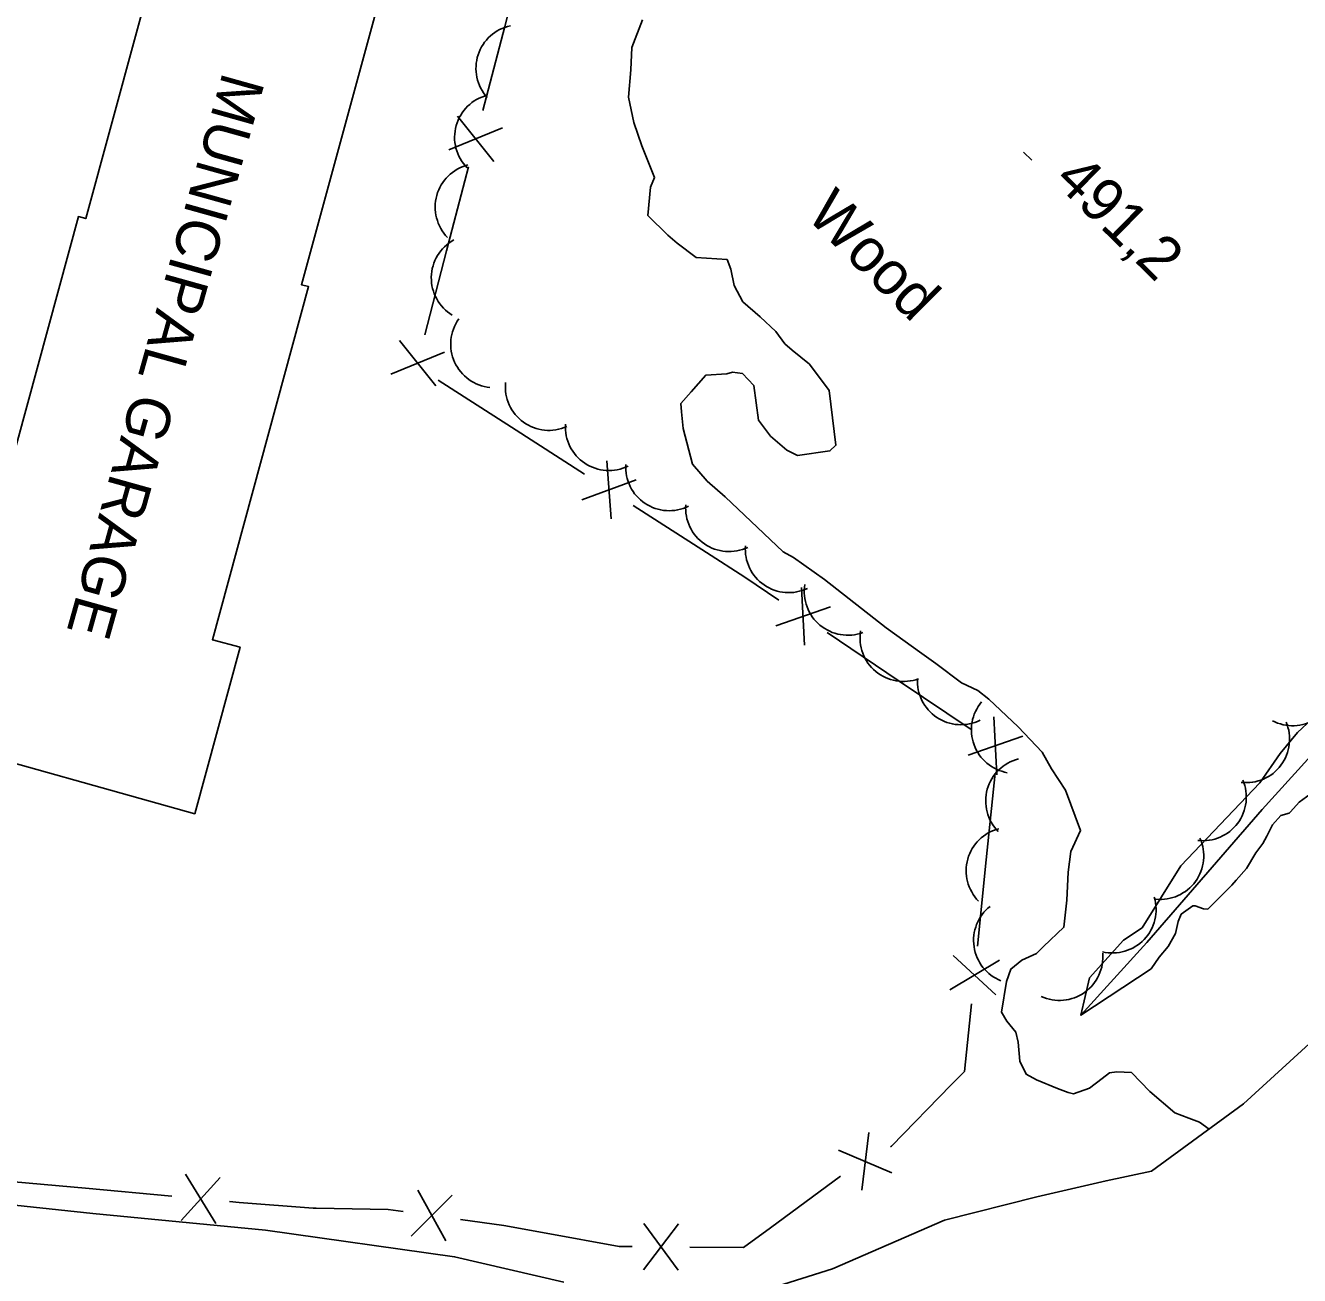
# Model space of a CAD drawing. Extents: x 642515 to 647219, y 6080136 to 6084356.
# Drawn here: x 643658.8 to 643746.7, y 6081612.4 to 6081698.7 of the extents above; entities that cross this region are included whole.
import ezdxf

# ---------------------------------------------------------------- set-up
doc = ezdxf.new("R2010")
doc.units = 0
for name, color, linetype in [('Level 1', 7, 'Continuous'), ('Level 19', 7, 'Continuous'), ('Level 2', 7, 'Continuous'), ('Level 3', 7, 'Continuous'), ('Level 31', 7, 'Continuous'), ('Level 37', 7, 'Continuous'), ('Level 4', 7, 'Continuous'), ('Level 44', 7, 'Continuous')]:
    doc.layers.add(name, color=color, linetype=linetype)

msp = doc.modelspace()

# ---------------------------------------------------------------- linework, layer by layer
at = {"layer": 'Level 1'}
msp.add_lwpolyline([(643747.429, 6081645.636), (643746.659, 6081645.102), (643746.061, 6081644.418), (643745.986, 6081644.332), (643745.393, 6081644.172), (643744.832, 6081643.531), (643744.443, 6081642.74), (643744.155, 6081642.238), (643743.674, 6081641.602), (643743.023, 6081640.511), (643742.313, 6081639.699), (643742.014, 6081639.357), (643740.353, 6081637.716), (643740.069, 6081637.738), (643739.491, 6081637.942), (643739.331, 6081637.931), (643738.524, 6081637.354), (643738.316, 6081636.857), (643738.13, 6081636.039), (643737.628, 6081635.12), (643736.993, 6081634.393), (643736.443, 6081633.591), (643731.596, 6081630.381), (643732.186, 6081632.958), (643734.547, 6081635.571), (643735.819, 6081636.42), (643738.509, 6081640.707), (643743.962, 6081646.425), (643745.355, 6081648.45), (643746.546, 6081649.899), (643748.592, 6081651.806)], dxfattribs=at)
at = {"layer": 'Level 19'}
for points in [[(643748.154, 6081629.154), (643742.826, 6081624.278), (643736.477, 6081619.617), (643733.333, 6081618.964), (643728.567, 6081617.84), (643722.18, 6081616.245), (643714.459, 6081612.868), (643708.535, 6081611.022)], [(643695.902, 6081611.955), (643688.373, 6081613.712), (643675.32, 6081615.544), (643663.399, 6081616.686), (643645.712, 6081618.573), (643643.905, 6081619.098), (643643.077, 6081620.655), (643642.485, 6081622.886)]]:
    msp.add_lwpolyline(points, dxfattribs=at)
at = {"layer": 'Level 2'}
for points in [[(643704.704, 6081673.419), (643705.712, 6081674.571), (643707.154, 6081674.666), (643707.549, 6081674.773), (643708.238, 6081674.697), (643709.018, 6081673.864), (643709.342, 6081671.472), (643710.181, 6081670.362), (643711.293, 6081669.389), (643712.041, 6081669.036), (643714.273, 6081669.344), (643714.689, 6081669.734), (643714.23, 6081673.524), (643712.861, 6081675.324), (643711.669, 6081676.291), (643711.156, 6081676.74), (643710.536, 6081677.583), (643709.461, 6081678.598), (643708.264, 6081679.645), (643707.664, 6081680.772), (643707.428, 6081681.883), (643707.181, 6081682.55), (643705.04, 6081682.69), (643703.725, 6081683.689), (643703.084, 6081684.25), (643701.705, 6081685.607), (643701.894, 6081687.55), (643702.171, 6081688.211), (643701.298, 6081690.406), (643700.746, 6081692.018), (643700.386, 6081693.764), (643700.539, 6081695.664), (643700.596, 6081697.195), (643701.352, 6081699.095)], [(643740.446, 6081622.53), (643739.789, 6081623.003), (643739.046, 6081623.276), (643738.095, 6081623.655), (643736.347, 6081625.109), (643735.09, 6081626.434), (643734.081, 6081626.488), (643733.563, 6081626.414), (643733.067, 6081626.019), (643732.187, 6081625.357), (643731.087, 6081624.963), (643730.718, 6081625.059), (643729.976, 6081625.332), (643728.528, 6081625.921), (643727.817, 6081626.316), (643727.394, 6081627.213), (643727.264, 6081628.532), (643727.098, 6081629.205), (643726.483, 6081629.969), (643726.119, 6081630.589), (643726.458, 6081632.703), (643726.761, 6081633.567), (643727.524, 6081634.181), (643728.538, 6081634.65), (643729.028, 6081635.125), (643730.426, 6081636.464), (643730.621, 6081638.327), (643730.731, 6081640.265), (643730.916, 6081641.685), (643731.581, 6081643.136), (643730.547, 6081645.924), (643729.562, 6081647.387), (643728.92, 6081648.552), (643727.273, 6081650.293), (643725.252, 6081652.211), (643724.488, 6081652.804), (643723.366, 6081653.334), (643721.586, 6081654.664), (643720.613, 6081655.364), (643718.16, 6081657.133), (643713.91, 6081660.473), (643711.757, 6081661.98), (643711.046, 6081662.375), (643707.047, 6081666.173), (643705.807, 6081667.258), (643704.801, 6081668.438), (643704.152, 6081670.889), (643704.033, 6081672.048), (643703.995, 6081672.608), (643704.704, 6081673.419)]]:
    msp.add_lwpolyline(points, dxfattribs=at)
at = {"layer": 'Level 3'}
msp.add_line((643727.634, 6081689.98), (643728.205, 6081689.421), dxfattribs=at)
at = {"layer": 'Level 31'}
msp.add_lwpolyline([(643652.541, 6081649.31), (643662.405, 6081685.523), (643662.913, 6081685.384), (643668.165, 6081704.664), (643683.179, 6081700.575), (643677.798, 6081680.821), (643678.298, 6081680.685), (643671.659, 6081656.312), (643673.566, 6081655.792), (643670.435, 6081644.297), (643652.541, 6081649.31)], dxfattribs=at)
at = {"layer": 'Level 37'}
for p, q in [((643690.328, 6081692.839), (643691.83, 6081698.648)), ((643688.581, 6081692.461), (643691.078, 6081689.336)), ((643687.98, 6081690.137), (643691.679, 6081691.659)), ((643687.823, 6081683.158), (643689.326, 6081688.967)), ((643686.321, 6081677.349), (643687.823, 6081683.158)), ((643684.575, 6081676.97), (643687.072, 6081673.845)), ((643683.974, 6081674.647), (643687.673, 6081676.169)), ((643692.288, 6081670.985), (643687.24, 6081674.229)), ((643697.335, 6081667.741), (643692.288, 6081670.985)), ((643699.168, 6081664.666), (643698.879, 6081668.656)), ((643697.149, 6081665.964), (643700.898, 6081667.358)), ((643705.748, 6081662.335), (643700.7, 6081665.578)), ((643712.529, 6081655.927), (643712.325, 6081659.922)), ((643710.538, 6081657.267), (643714.316, 6081658.581)), ((643719.058, 6081653.456), (643714.08, 6081656.806)), ((643724.035, 6081650.105), (643719.058, 6081653.456)), ((643725.802, 6081646.992), (643725.598, 6081650.987)), ((643723.811, 6081648.332), (643727.589, 6081649.647)), ((643725.073, 6081641.123), (643725.687, 6081647.092)), ((643724.459, 6081635.155), (643725.073, 6081641.123)), ((643722.544, 6081632.131), (643725.973, 6081634.191)), ((643722.789, 6081634.518), (643725.727, 6081631.803)), ((643716.954, 6081622.278), (643716.476, 6081618.307)), ((643714.876, 6081621.078), (643718.554, 6081619.508)), ((643656.912, 6081618.987), (643662.887, 6081618.437)), ((643672.19, 6081619.184), (643669.507, 6081616.217)), ((643669.8, 6081619.404), (643671.897, 6081615.998)), ((643710.172, 6081615.711), (643715.007, 6081619.264)), ((643662.887, 6081618.437), (643668.862, 6081617.888)), ((643685.826, 6081618.306), (643687.759, 6081614.804)), ((643688.203, 6081617.973), (643685.382, 6081615.137)), ((643703.827, 6081615.983), (643701.401, 6081612.802)), ((643701.427, 6081616.002), (643703.801, 6081612.783))]:
    msp.add_line(p, q, dxfattribs=at)
for points in [[(643691.83, 6081698.648), (643693.16, 6081703.79), (643692.501, 6081703.989)], [(643710.762, 6081659.04), (643708.4, 6081660.63), (643705.748, 6081662.335)], [(643722.655, 6081625.573), (643723.57, 6081626.51), (643724.05, 6081631.176)], [(643718.448, 6081621.299), (643718.52, 6081621.34), (643722.655, 6081625.573)], [(643672.845, 6081617.521), (643673.51, 6081617.46), (643678.6, 6081617.07), (643678.827, 6081617.066)], [(643678.827, 6081617.066), (643683.79, 6081616.98), (643684.816, 6081616.836)], [(643688.777, 6081616.281), (643691.78, 6081615.86), (643694.7, 6081615.33)], [(643704.618, 6081614.38), (643708.32, 6081614.35), (643710.172, 6081615.711)], [(643694.7, 6081615.33), (643699.72, 6081614.42), (643700.619, 6081614.413)]]:
    msp.add_lwpolyline(points, dxfattribs=at)
at = {"layer": 'Level 4'}
msp.add_lwpolyline([(643752.671, 6081654.027), (643744.116, 6081644.599), (643736.153, 6081635.414), (643731.596, 6081630.381)], dxfattribs=at)
at = {"layer": 'Level 44'}
for centre, start, end in [((643692.846, 6081695.76), 102.01503, 221.99298), ((643691.371, 6081690.997), 104.47219, 224.45014), ((643690.031, 6081686.18), 104.47219, 224.45014), ((643689.763, 6081681.281), 118.85814, 238.83608), ((643691.102, 6081676.716), 144.52676, 264.5047), ((643694.874, 6081673.763), 174.38524, 294.36319), ((643699.021, 6081670.988), 176.31726, 296.2952), ((643703.181, 6081668.214), 176.31726, 296.2952), ((643707.316, 6081665.396), 175.48626, 295.46421), ((643711.435, 6081662.561), 175.48626, 295.46421), ((643715.509, 6081659.622), 170.29802, 290.27597), ((643719.354, 6081656.427), 170.29802, 290.27597), ((643723.318, 6081653.441), 176.2285, 296.20645), ((643746.219, 6081653.37), 242.1321, 2.11005), ((643727.042, 6081650.085), 139.96469, 259.94264), ((643743.006, 6081649.442), 263.31936, 23.29731), ((643728.029, 6081645.174), 104.39223, 224.37018), ((643740.017, 6081645.434), 263.31936, 23.29731), ((643726.682, 6081640.359), 104.39223, 224.37018), ((643737.079, 6081641.383), 264.083, 24.06095), ((643733.788, 6081637.684), 256.42447, 16.40242), ((643727.191, 6081635.549), 128.30618, 248.28413), ((643730.119, 6081634.408), 245.20842, 5.18637)]:
    msp.add_arc(centre, 3, start, end, dxfattribs=at)

# ---------------------------------------------------------------- texts
at = {"layer": 'Level 3'}
msp.add_text('491,2', height=3, rotation=315.59, dxfattribs=at).set_placement((643729.66, 6081687.94))
at = {"layer": 'Level 31'}
msp.add_text('MUNICIPAL GARAGE', height=3, rotation=254.38081, dxfattribs=at).set_placement((643672.39, 6081695.58))
at = {"layer": 'Level 44'}
msp.add_text('Wood', height=2.9999, rotation=315.1749, dxfattribs=at).set_placement((643712.55, 6081685.52))

doc.saveas('drawing.dxf')
